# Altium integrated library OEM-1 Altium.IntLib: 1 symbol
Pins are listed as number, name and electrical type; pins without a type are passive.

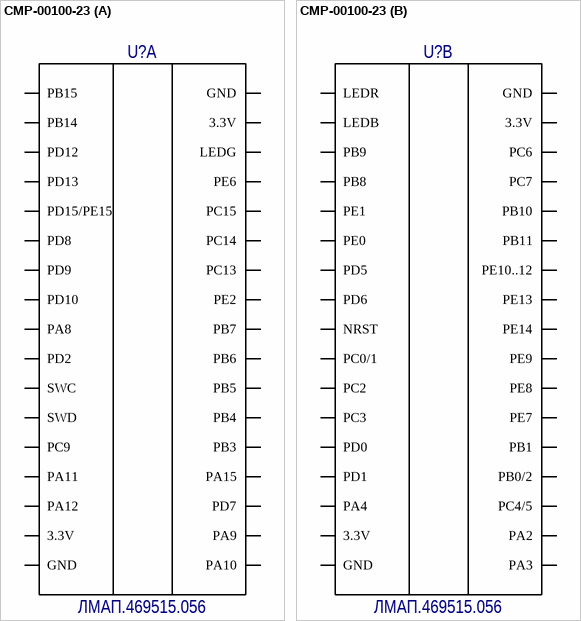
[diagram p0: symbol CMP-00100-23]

## CMP-00100-23
designator U?, comment ЛМАП.469515.056
Инерциальный модуль на основе микроконтроллера STM32F765VGH6 и датчиков: BMG250, ADXL357BEZ, MMC5983MA, BMP388. Также содержит RGB-светодиод APTF1616LSEEZGKQBKC; Manufacturer: ЛМП; Код: БП-00004214; Наименование: Модуль инерциальный ГКВ-1-OEM ЛМАП.469515.056
footprint Модуль инерциальный ГКВ-1-OEM ЛМАП.469515.056
footprint Модуль инерциальный ГКВ-1-OEM ЛМАП.469515.056
part A pins: 1 PB15, 2 PB14, 3 PD12, 4 PD13, 5 PD15/PE15, 6 PD8, 7 PD9, 8 PD10, 9 PA8, 10 PD2, 11 SWC, 12 SWD, 13 PC9, 14 PA11, 15 PA12, 16 3.3V, 17 GND, 18 PA10, 19 PA9, 20 PD7, 21 PA15, 22 PB3, 23 PB4, 24 PB5, 25 PB6, 26 PB7, 27 PE2, 28 PC13, 29 PC14, 30 PC15, 31 PE6, 32 LEDG, 33 3.3V, 34 GND
part B pins: 35 LEDR, 36 LEDB, 37 PB9, 38 PB8, 39 PE1, 40 PE0, 41 PD5, 42 PD6, 43 NRST, 44 PC0/1, 45 PC2, 46 PC3, 47 PD0, 48 PD1, 49 PA4, 50 3.3V, 51 GND, 52 PA3, 53 PA2, 54 PC4/5, 55 PB0/2, 56 PB1, 57 PE7, 58 PE8, 59 PE9, 60 PE14, 61 PE13, 62 PE10..12, 63 PB11, 64 PB10, 65 PC7, 66 PC6, 67 3.3V, 68 GND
